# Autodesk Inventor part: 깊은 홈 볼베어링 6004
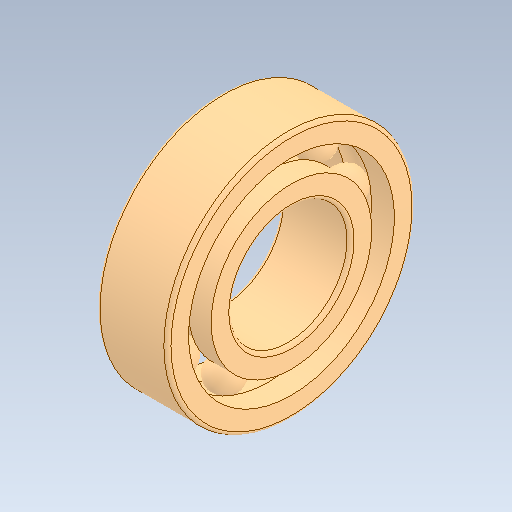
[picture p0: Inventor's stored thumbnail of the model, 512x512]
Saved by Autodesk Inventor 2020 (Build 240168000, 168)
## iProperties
Created: 2024-09
Part Number: 깊은 홈 볼베어링 6004
Material: 강철, 연강
Description: 깊은 그루브 볼 베어링
Document SubType Name: Modeling
Designer: oem
Density: 7.85 g/cm^3
Appearance: 기본값
Author: jhkim
Sending System: Autodesk Inventor 2025
Preprocessor: ST-DEVELOPER v20
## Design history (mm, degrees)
feature "Solid1"
feature "Solid1:1"
feature "Solid1:2"
feature "Solid1:3"
feature "Solid1:4"
feature "Solid1:5"
feature "Solid1:6"
feature "Solid1:7"
feature "Solid1:8"
feature "Solid1:9"
feature "Solid1:10"
node "솔리드1"
node "솔리드2"
node "솔리드3"
node "솔리드4"
node "솔리드5"
node "솔리드6"
node "솔리드7"
node "솔리드8"
node "솔리드9"
node "솔리드10"
node "솔리드11"
